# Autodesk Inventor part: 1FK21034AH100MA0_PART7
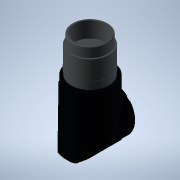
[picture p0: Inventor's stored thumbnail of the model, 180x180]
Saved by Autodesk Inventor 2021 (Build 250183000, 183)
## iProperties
Created: 2025-04
Part Number: 1FK21034AH100MA0_PART7
Material: Generic
Catalog Web Link: www.3dfindit.com
Description: -Servo synchronous motor
Document SubType Name: Modeling
Designer: psAdmin
Mass: 11.1504 g
Surface Area: 35.8996 cm^2
Volume: 11.1504 cm^3
Density: 1 g/cm^3
Appearance: PSOLRGB-176-176-176
Category: PARTsolutions
Title: 1FK21034AH100MA0_PART7
Author: Cadenas PARTsolutions
Comments: Servo synchronous motor
Sending System: PARTsolutions
Preprocessor: ST-DEVELOPER v19.3
PSOL_IDENT_0: {$CADENAS_DATA/23d-libs/siemens_ag/_cat_/39/97/1fk21034ah100ma0.prj},213 {VTYP=3D},{NB=1FK21034AH100
PSOL_IDENT_1: MA0_PART7},{LINA=1FK21034AH100MA0_PART7},{NN=1FK21034AH100MA0_PART7},{NOPRJ=TRUE},{DATE=19.08.2025 1
PSOL_IDENT_2: 4:00:33},{GEOMDATE=30.07.2025 02:02:21},{VERSION=},{LINEID=10},{WBVAR=},{WBNUMERIC=}  {NB=1FK21034AH
PSOL_IDENT_3: 100MA0_PART7},{LINA=1FK21034AH100MA0_PART7},{KT=DUMMY},{PREVIEW=../../../_pool_/d3/78/p_d211_xx_0093
PSOL_IDENT_4: 4j.png},{DESCSHORT=SIMOTICS S-1FK2 HD, SINAMICS S210 3AC 400V-480V, 1.01 Nm, 4500 rpm},{DESCLONG=SIM
PSOL_IDENT_5: OTICS S-1FK2 HD servo motor M0=1.27 Nm; PN = 0.48 kW at nN=4500 rpm (380-480 V); PN = 0.3 kW at nN=2
PSOL_IDENT_6: 500 rpm (200-240 V); with holding brake; degree of protection IP64; cylindrical shaft D14 x 30 mm; a
PSOL_IDENT_7: bsolute encoder 22-bit + 12-bit multiturn (encoder AM22DQC); with OCC interface; plug size M17, rota
PSOL_IDENT_8: table; SIMOTICS S-1FK2 servomotorfor a wide range of uses in industrial environments. SIMOTICS S‑1FK
PSOL_IDENT_9: 2 servomotors are compact synchronous motors with a high dynamic performance that set themselves apa
PSOL_IDENT_10: rt as a result of their high power density, degree of protection and overload capability. The motors
PSOL_IDENT_11: are available in two variants: as High Dynamic variant (highest dynamic performance as a result of
PSOL_IDENT_12: the low intrinsic moment of inertia for applications demanding a high dynamic performance with low m
PSOL_IDENT_13: oved masses) - and as Compact variant (precise and stable closed-loop control for medium up to large
PSOL_IDENT_14: moved masses as a result of a medium intrinsic moment of inertia). SIMOTICSS‑1FK2 servomotors fully
PSOL_IDENT_15: exploit their strengths in a system with the SINAMICSS210 frequency converter and simple connection
PSOL_IDENT_16: using the one cable connection (OCC). Advantages include the short control and positioning times, f
PSOL_IDENT_17: ast and precise correction of disturbing quantities as well as stable control with a high dynamic pe
PSOL_IDENT_18: rformance. The servo motors can be configured to address a wide range of requirements. For example w
PSOL_IDENT_19: ith and without holding brake, IP64 or IP65 degree of protection, singleturn or multiturn absolute e
PSOL_IDENT_20: ncoders - to name just a few. Further, the servomotors are available in different shaft heights exte
PSOL_IDENT_21: nding from 20 to 100. A shaft sealing ring is available to achieve an IP65 degree of protection and
PSOL_IDENT_22: for subsequent mounting at the motor or as spare part. SIMOTICS - the optimum motor for each and eve
PSOL_IDENT_23: ry motion control application.},{INTNO=195125454019},{SUPPLIERALTNO=1FK2103-4AH10-0MA0},{MANUID=1FK2
PSOL_IDENT_24: 1034AH100MA0},{MANUNAME=Siemens},{MANUTYPEDESC=SYNCHRONOUS MOTOR 1FK2 HD 1,27 NM},{AAU732=SIMOTICS},
PSOL_IDENT_25: {AAO057=S-1FK2},{AAU734=SIMOTICS S-1FK2 HD servo motor M0=1.27 Nm; PN = 0.48 kW at nN=4500 rpm (380-
PSOL_IDENT_26: 480 V); PN = 0.3 kW at nN=2500 rpm (200-240 V); with holding brake; degree of protection IP64; cylin
PSOL_IDENT_27: drical shaft D14 x 30 mm; absolute encoder 22-bit + 12-bit multiturn (encoder AM22DQC); with OCC int
PSOL_IDENT_28: erface; plug size M17, rotatable;},{AAW338=SYNCHRONOUS MOTOR 1FK2 HD 1,27 NM},{AAO742=SIMOTICS},{AAO
PSOL_IDENT_29: 663=4034106444921},{NOCUPEROU=1},{PRICEQUANTITY=1},{QUANTITYMIN=1},{QUANTITYINT=1},{CTN=85015100},{C
PSOL_IDENT_30: OO=RO},{AAO676=1FK2103-4AH10-0MA0},{AAO677=Siemens AG},{ORDERUNIT=C62},{CONTENTUNIT=C62}
NB: 1FK21034AH100MA0_PART7
NT: Servo synchronous motor
NBSYN: $MANUID._PART7
LINA: 1FK21034AH100MA0_PART7
CATALOG: SIEMENS
PREVIEW: ../../../_pool_/d3/78/p_d211_xx_00934j.png
DESCSHORT: SIMOTICS S-1FK2 HD, SINAMICS S210 3AC 400V-480V, 1.01 Nm, 4500 rpm
DESCLONG: SIMOTICS S-1FK2 HD servo motor M0=1.27 Nm; PN = 0.48 kW at nN=4500 rpm (380-480 V); PN = 0.3 kW at nN=2500 rpm (200-240 V); with holding brake; degree of protec
INTNO: 195125454019
SUPPLIERALTNO: 1FK2103-4AH10-0MA0
MANUID: 1FK21034AH100MA0
MANUNAME: Siemens
MANUTYPEDESC: SYNCHRONOUS MOTOR 1FK2 HD 1,27 NM
AAU732: SIMOTICS
AAO057: S-1FK2
AAU734: SIMOTICS S-1FK2 HD servo motor M0=1.27 Nm; PN = 0.48 kW at nN=4500 rpm (380-480 V); PN = 0.3 kW at nN=2500 rpm (200-240 V); with holding brake; degree of protec
AAW338: SYNCHRONOUS MOTOR 1FK2 HD 1,27 NM
AAO742: SIMOTICS
AAO663: 4034106444921.0
NOCUPEROU: 1
PRICEQUANTITY: 1
QUANTITYMIN: 1
QUANTITYINT: 1
CTN: 85015100
COO: RO
ARTICLENO: 1FK21034AH100MA0_PART7
BOMINFO: 1FK21034AH100MA0_PART7
CREATOR: CADENAS GmbH
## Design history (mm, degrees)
feature "2025_04_17_15_09_00_0330"
body "Solid1"
